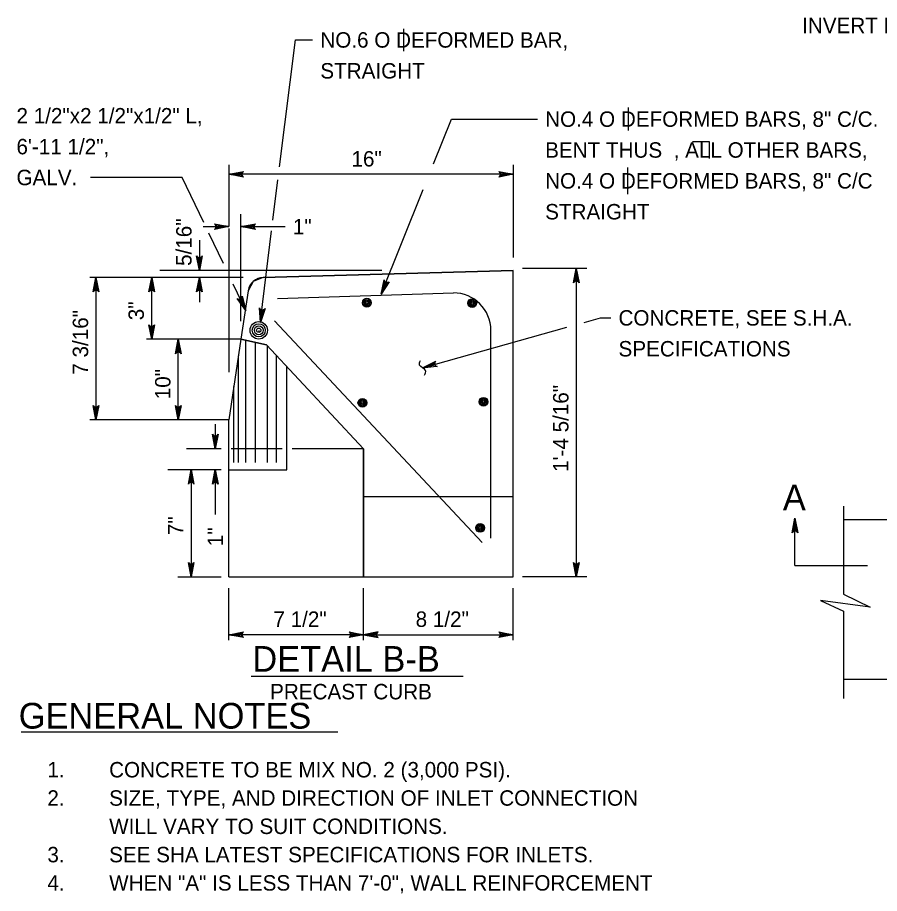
# Model space of a CAD drawing. Extents: x 2.4 to 9.7, y 1.1 to 11.2.
# Drawn here: x 2.448 to 5.797, y 4.792 to 8.197 of the extents above; entities that cross this region are included whole.
import ezdxf

# ---------------------------------------------------------------- set-up
doc = ezdxf.new("R2010")
doc.units = 0
for name, color, linetype in [('DETL-DIMS', 7, 'Continuous'), ('DETL-LINE', 7, 'Continuous'), ('DETL-NOTE', 7, 'Continuous'), ('DETL-PATT', 7, 'Continuous'), ('DETL-TITL', 7, 'Continuous')]:
    doc.layers.add(name, color=color, linetype=linetype)

msp = doc.modelspace()

# ---------------------------------------------------------------- linework, layer by layer
at = {"layer": 'DETL-DIMS'}
for p, q in [((3.466, 7.6169), (3.5274, 8.1102)), ((3.5274, 8.1102), (3.5939, 8.1102)), ((4.064, 7.6283), (4.134, 7.8024)), ((4.134, 7.8024), (4.4675, 7.8024)), ((3.2692, 7.6252), (3.2692, 7.3843)), ((4.3741, 7.6252), (4.3741, 7.265)), ((3.0872, 7.5755), (2.7316, 7.5755)), ((3.1714, 7.4), (3.0872, 7.5755)), ((4.3741, 7.5878), (3.2692, 7.5878)), ((3.4402, 7.4102), (3.4597, 7.5668)), ((3.8604, 7.1217), (4.0242, 7.5292)), ((3.3158, 7.017), (3.3158, 7.4334)), ((3.1685, 7.3843), (3.2692, 7.3843)), ((3.2478, 7.2406), (3.1908, 7.3595)), ((3.2692, 7.3772), (3.2692, 6.8182)), ((3.3158, 7.3843), (3.4874, 7.3843)), ((3.3927, 7.0288), (3.4349, 7.3676)), ((3.1543, 7.3314), (3.1543, 7.214)), ((4.6598, 7.222), (4.4098, 7.222)), ((4.6187, 7.222), (4.6187, 6.0227)), ((3.3242, 7.1873), (2.7288, 7.1873)), ((2.7524, 7.1873), (2.7524, 6.6331)), ((2.969, 6.9464), (2.969, 7.1873)), ((3.8631, 7.214), (3.0002, 7.214)), ((3.1543, 7.1873), (3.1543, 7.0908)), ((3.335, 7.0585), (3.2862, 7.1605)), ((4.6497, 7.0121), (4.7123, 7.0297)), ((4.7123, 7.0297), (4.7525, 7.0297)), ((3.3859, 6.9743), (3.3867, 6.9812)), ((4.0216, 6.8356), (4.5823, 6.9932)), ((3.316, 6.9464), (2.9483, 6.9464)), ((3.0724, 6.6331), (3.0724, 6.9464)), ((3.2692, 6.6331), (2.7288, 6.6331)), ((3.2162, 6.6167), (3.2162, 6.5207)), ((3.2395, 6.5207), (3.1038, 6.5207)), ((3.4756, 6.5207), (3.2777, 6.5207)), ((3.7923, 6.5207), (3.5142, 6.5207)), ((3.0316, 6.44), (3.2395, 6.44)), ((3.1221, 6.44), (3.1221, 6.0227)), ((3.2162, 6.44), (3.2162, 6.2651)), ((5.4685, 6.0667), (5.4683, 6.2512)), ((5.4685, 6.0667), (5.7503, 6.0671)), ((3.0705, 6.0227), (3.2395, 6.0227)), ((4.6598, 6.0227), (4.4098, 6.0227)), ((3.2692, 5.7764), (3.2692, 5.9792)), ((3.7923, 5.7764), (3.7923, 5.9792)), ((4.3741, 5.7764), (4.3741, 5.9792)), ((3.7923, 5.7981), (3.2692, 5.7981)), ((3.7923, 5.7981), (4.3741, 5.7981))]:
    msp.add_line(p, q, dxfattribs=at)
for points in [[(3.2692, 7.5878), (3.3257, 7.5983), (3.3213, 7.5953), (3.3191, 7.5915), (3.3185, 7.5878), (3.3191, 7.584), (3.3213, 7.5802), (3.3257, 7.5772), (3.2692, 7.5878), (3.3213, 7.5802), (3.3191, 7.584), (3.2692, 7.5878), (3.3185, 7.5878), (3.3191, 7.5915), (3.2692, 7.5878), (3.3213, 7.5953)], [(4.3741, 7.5878), (4.3176, 7.5772), (4.322, 7.5802), (4.3242, 7.584), (4.3249, 7.5878), (4.3242, 7.5915), (4.322, 7.5953), (4.3176, 7.5983), (4.3741, 7.5878), (4.322, 7.5953), (4.3242, 7.5915), (4.3741, 7.5878), (4.3249, 7.5878), (4.3242, 7.584), (4.3741, 7.5878), (4.322, 7.5802)], [(3.2692, 7.3843), (3.2127, 7.3737), (3.2171, 7.3767), (3.2193, 7.3805), (3.22, 7.3843), (3.2193, 7.388), (3.2171, 7.3918), (3.2127, 7.3948), (3.2692, 7.3843), (3.2171, 7.3918), (3.2193, 7.388), (3.2692, 7.3843), (3.22, 7.3843), (3.2193, 7.3805), (3.2692, 7.3843), (3.2171, 7.3767)], [(3.3158, 7.3843), (3.3722, 7.3948), (3.3679, 7.3918), (3.3657, 7.388), (3.365, 7.3843), (3.3657, 7.3805), (3.3679, 7.3767), (3.3722, 7.3737), (3.3158, 7.3843), (3.3679, 7.3767), (3.3657, 7.3805), (3.3158, 7.3843), (3.365, 7.3843), (3.3657, 7.388), (3.3158, 7.3843), (3.3679, 7.3918)], [(3.1543, 7.214), (3.1437, 7.2705), (3.1467, 7.2661), (3.1505, 7.2639), (3.1543, 7.2632), (3.1581, 7.2639), (3.1619, 7.2661), (3.1649, 7.2705), (3.1543, 7.214), (3.1619, 7.2661), (3.1581, 7.2639), (3.1543, 7.214), (3.1543, 7.2632), (3.1505, 7.2639), (3.1543, 7.214), (3.1467, 7.2661)], [(4.6187, 7.222), (4.6293, 7.1655), (4.6263, 7.1698), (4.6225, 7.1721), (4.6187, 7.1727), (4.6149, 7.1721), (4.6112, 7.1698), (4.6081, 7.1655), (4.6187, 7.222), (4.6112, 7.1698), (4.6149, 7.1721), (4.6187, 7.222), (4.6187, 7.1727), (4.6225, 7.1721), (4.6187, 7.222), (4.6263, 7.1698)], [(2.7524, 7.1873), (2.763, 7.1308), (2.7599, 7.1352), (2.7562, 7.1374), (2.7524, 7.1381), (2.7486, 7.1374), (2.7448, 7.1352), (2.7418, 7.1308), (2.7524, 7.1873), (2.7448, 7.1352), (2.7486, 7.1374), (2.7524, 7.1873), (2.7524, 7.1381), (2.7562, 7.1374), (2.7524, 7.1873), (2.7599, 7.1352)], [(2.969, 7.1873), (2.9796, 7.1308), (2.9766, 7.1352), (2.9728, 7.1374), (2.969, 7.1381), (2.9652, 7.1374), (2.9615, 7.1352), (2.9584, 7.1308), (2.969, 7.1873), (2.9615, 7.1352), (2.9652, 7.1374), (2.969, 7.1873), (2.969, 7.1381), (2.9728, 7.1374), (2.969, 7.1873), (2.9766, 7.1352)], [(3.1543, 7.1873), (3.1649, 7.1308), (3.1619, 7.1352), (3.1581, 7.1374), (3.1543, 7.1381), (3.1505, 7.1374), (3.1467, 7.1352), (3.1437, 7.1308), (3.1543, 7.1873), (3.1467, 7.1352), (3.1505, 7.1374), (3.1543, 7.1873), (3.1543, 7.1381), (3.1581, 7.1374), (3.1543, 7.1873), (3.1619, 7.1352)], [(3.8604, 7.1217), (3.8717, 7.1781), (3.8729, 7.1729), (3.8755, 7.1694), (3.8788, 7.1674), (3.8826, 7.1666), (3.8869, 7.1672), (3.8913, 7.1702), (3.8604, 7.1217), (3.8869, 7.1672), (3.8826, 7.1666), (3.8604, 7.1217), (3.8788, 7.1674), (3.8755, 7.1694), (3.8604, 7.1217), (3.8729, 7.1729)], [(3.335, 7.0585), (3.3011, 7.1049), (3.3057, 7.1023), (3.3101, 7.1019), (3.3138, 7.1029), (3.3169, 7.1052), (3.3193, 7.1088), (3.3202, 7.1141), (3.335, 7.0585), (3.3193, 7.1088), (3.3169, 7.1052), (3.335, 7.0585), (3.3138, 7.1029), (3.3101, 7.1019), (3.335, 7.0585), (3.3057, 7.1023)], [(3.3918, 7.0116), (3.3883, 7.0689), (3.3908, 7.0642), (3.3943, 7.0615), (3.3979, 7.0604), (3.4018, 7.0606), (3.4058, 7.0624), (3.4093, 7.0663), (3.3918, 7.0116), (3.4058, 7.0624), (3.4018, 7.0606), (3.3918, 7.0116), (3.3979, 7.0604), (3.3943, 7.0615), (3.3918, 7.0116), (3.3908, 7.0642)], [(2.969, 6.9464), (2.9584, 7.0029), (2.9615, 6.9985), (2.9652, 6.9963), (2.969, 6.9956), (2.9728, 6.9963), (2.9766, 6.9985), (2.9796, 7.0029), (2.969, 6.9464), (2.9766, 6.9985), (2.9728, 6.9963), (2.969, 6.9464), (2.969, 6.9956), (2.9652, 6.9963), (2.969, 6.9464), (2.9615, 6.9985)], [(3.0724, 6.9464), (3.083, 6.8899), (3.0799, 6.8943), (3.0761, 6.8965), (3.0724, 6.8972), (3.0686, 6.8965), (3.0648, 6.8943), (3.0618, 6.8899), (3.0724, 6.9464), (3.0648, 6.8943), (3.0686, 6.8965), (3.0724, 6.9464), (3.0724, 6.8972), (3.0761, 6.8965), (3.0724, 6.9464), (3.0799, 6.8943)], [(4.0216, 6.8356), (4.0731, 6.8611), (4.0697, 6.857), (4.0686, 6.8528), (4.069, 6.8489), (4.0706, 6.8455), (4.0738, 6.8424), (4.0788, 6.8407), (4.0216, 6.8356), (4.0738, 6.8424), (4.0706, 6.8455), (4.0216, 6.8356), (4.069, 6.8489), (4.0686, 6.8528), (4.0216, 6.8356), (4.0697, 6.857)], [(2.7524, 6.6331), (2.7418, 6.6896), (2.7448, 6.6852), (2.7486, 6.683), (2.7524, 6.6823), (2.7562, 6.683), (2.7599, 6.6852), (2.763, 6.6896), (2.7524, 6.6331), (2.7599, 6.6852), (2.7562, 6.683), (2.7524, 6.6331), (2.7524, 6.6823), (2.7486, 6.683), (2.7524, 6.6331), (2.7448, 6.6852)], [(3.0724, 6.6331), (3.0618, 6.6896), (3.0648, 6.6852), (3.0686, 6.683), (3.0724, 6.6823), (3.0761, 6.683), (3.0799, 6.6852), (3.083, 6.6896), (3.0724, 6.6331), (3.0799, 6.6852), (3.0761, 6.683), (3.0724, 6.6331), (3.0724, 6.6823), (3.0686, 6.683), (3.0724, 6.6331), (3.0648, 6.6852)], [(3.2162, 6.5207), (3.2056, 6.5771), (3.2086, 6.5728), (3.2124, 6.5705), (3.2162, 6.5699), (3.22, 6.5705), (3.2238, 6.5728), (3.2268, 6.5771), (3.2162, 6.5207), (3.2238, 6.5728), (3.22, 6.5705), (3.2162, 6.5207), (3.2162, 6.5699), (3.2124, 6.5705), (3.2162, 6.5207), (3.2086, 6.5728)], [(3.1221, 6.44), (3.1327, 6.3835), (3.1296, 6.3879), (3.1259, 6.3901), (3.1221, 6.3908), (3.1183, 6.3901), (3.1145, 6.3879), (3.1115, 6.3835), (3.1221, 6.44), (3.1145, 6.3879), (3.1183, 6.3901), (3.1221, 6.44), (3.1221, 6.3908), (3.1259, 6.3901), (3.1221, 6.44), (3.1296, 6.3879)], [(3.2162, 6.44), (3.2268, 6.3835), (3.2238, 6.3879), (3.22, 6.3901), (3.2162, 6.3908), (3.2124, 6.3901), (3.2086, 6.3879), (3.2056, 6.3835), (3.2162, 6.44), (3.2086, 6.3879), (3.2124, 6.3901), (3.2162, 6.44), (3.2162, 6.3908), (3.22, 6.3901), (3.2162, 6.44), (3.2238, 6.3879)], [(5.4683, 6.2512), (5.479, 6.1947), (5.4759, 6.199), (5.4721, 6.2013), (5.4684, 6.2019), (5.4646, 6.2013), (5.4608, 6.199), (5.4578, 6.1947), (5.4683, 6.2512), (5.4608, 6.199), (5.4646, 6.2013), (5.4683, 6.2512), (5.4684, 6.2019), (5.4721, 6.2013), (5.4683, 6.2512), (5.4759, 6.199)], [(3.1221, 6.0227), (3.1115, 6.0792), (3.1145, 6.0748), (3.1183, 6.0726), (3.1221, 6.0719), (3.1259, 6.0726), (3.1296, 6.0748), (3.1327, 6.0792), (3.1221, 6.0227), (3.1296, 6.0748), (3.1259, 6.0726), (3.1221, 6.0227), (3.1221, 6.0719), (3.1183, 6.0726), (3.1221, 6.0227), (3.1145, 6.0748)], [(4.6187, 6.0227), (4.6081, 6.0792), (4.6112, 6.0748), (4.6149, 6.0726), (4.6187, 6.0719), (4.6225, 6.0726), (4.6263, 6.0748), (4.6293, 6.0792), (4.6187, 6.0227), (4.6263, 6.0748), (4.6225, 6.0726), (4.6187, 6.0227), (4.6187, 6.0719), (4.6149, 6.0726), (4.6187, 6.0227), (4.6112, 6.0748)], [(5.6575, 5.9558), (5.7602, 5.9055), (5.568, 5.9316), (5.6575, 5.8891)], [(3.2692, 5.7981), (3.3257, 5.8087), (3.3213, 5.8057), (3.3191, 5.8019), (3.3185, 5.7981), (3.3191, 5.7944), (3.3213, 5.7906), (3.3257, 5.7876), (3.2692, 5.7981), (3.3213, 5.7906), (3.3191, 5.7944), (3.2692, 5.7981), (3.3185, 5.7981), (3.3191, 5.8019), (3.2692, 5.7981), (3.3213, 5.8057)], [(3.7923, 5.7981), (3.7358, 5.7876), (3.7402, 5.7906), (3.7424, 5.7944), (3.7431, 5.7981), (3.7424, 5.8019), (3.7402, 5.8057), (3.7358, 5.8087), (3.7923, 5.7981), (3.7402, 5.8057), (3.7424, 5.8019), (3.7923, 5.7981), (3.7431, 5.7981), (3.7424, 5.7944), (3.7923, 5.7981), (3.7402, 5.7906)], [(3.7923, 5.7981), (3.8488, 5.7876), (3.8445, 5.7906), (3.8422, 5.7944), (3.8416, 5.7981), (3.8422, 5.8019), (3.8445, 5.8057), (3.8488, 5.8087), (3.7923, 5.7981), (3.8445, 5.8057), (3.8422, 5.8019), (3.7923, 5.7981), (3.8416, 5.7981), (3.8422, 5.7944), (3.7923, 5.7981), (3.8445, 5.7906)], [(4.3741, 5.7981), (4.3176, 5.7876), (4.322, 5.7906), (4.3242, 5.7944), (4.3249, 5.7981), (4.3242, 5.8019), (4.322, 5.8057), (4.3176, 5.8087), (4.3741, 5.7981), (4.322, 5.8057), (4.3242, 5.8019), (4.3741, 5.7981), (4.3249, 5.7981), (4.3242, 5.7944), (4.3741, 5.7981), (4.322, 5.7906)]]:
    msp.add_lwpolyline(points, dxfattribs=at)
msp.add_spline([(4.029, 6.807), (4.033, 6.8251), (4.0101, 6.8462), (4.0132, 6.8639)], degree=3, dxfattribs=at)
at = {"layer": 'DETL-LINE'}
for p, q in [((3.4025, 7.187), (4.3741, 7.214)), ((4.3741, 6.0227), (4.3741, 7.214)), ((3.3442, 7.1353), (3.316, 6.9464)), ((3.4584, 7.1053), (4.1414, 7.1267)), ((4.2529, 6.156), (3.4462, 7.0186)), ((4.2869, 6.1737), (4.2869, 6.9813)), ((3.316, 6.9464), (3.2692, 6.6331)), ((3.4149, 6.9243), (3.316, 6.9464)), ((3.3351, 6.467), (3.3351, 6.9421)), ((3.3726, 6.467), (3.3726, 6.9337)), ((3.7923, 6.5207), (3.4149, 6.9243)), ((3.419, 6.467), (3.419, 6.9198)), ((3.3063, 6.467), (3.3063, 6.8818)), ((3.4543, 6.467), (3.4543, 6.882)), ((3.4938, 6.4388), (3.4938, 6.8398)), ((3.2887, 6.467), (3.2887, 6.7634)), ((3.2692, 6.0227), (3.2692, 6.6331)), ((3.7923, 6.0227), (3.7923, 6.5207)), ((3.2692, 6.4388), (3.4938, 6.4388)), ((3.7923, 6.3357), (4.3741, 6.3357)), ((5.6575, 6.2975), (5.6575, 5.9558)), ((6.0058, 6.2449), (5.6575, 6.2449)), ((3.2692, 6.0227), (4.3741, 6.0227)), ((5.6575, 5.8891), (5.6575, 5.5495)), ((6.0058, 5.6245), (5.6575, 5.6245))]:
    msp.add_line(p, q, dxfattribs=at)
for centre, radius in [((3.8053, 7.0888), 0.017), ((3.8053, 7.0888), 0.0127), ((3.8053, 7.0888), 0.00848), ((3.8053, 7.0888), 0.00424), ((4.2146, 7.0872), 0.017), ((4.2146, 7.0872), 0.0127), ((4.2146, 7.0872), 0.00848), ((4.2146, 7.0872), 0.00424), ((3.385, 6.9814), 0.0339), ((3.385, 6.9814), 0.0255), ((3.385, 6.9814), 0.017), ((3.385, 6.9814), 0.00848), ((3.7876, 6.6994), 0.017), ((3.7876, 6.6994), 0.0127), ((4.2583, 6.7038), 0.017), ((4.2583, 6.7038), 0.0127), ((4.2583, 6.7038), 0.00848), ((3.7876, 6.6994), 0.00848), ((3.7876, 6.6994), 0.00424), ((4.2583, 6.7038), 0.00424), ((4.2449, 6.2132), 0.017), ((4.2449, 6.2132), 0.0127), ((4.2449, 6.2132), 0.00848), ((4.2449, 6.2132), 0.00424)]:
    msp.add_circle(centre, radius, dxfattribs=at)
for centre, radius, start, end in [((3.4041, 7.1264), 0.0606, 91.5948, 171.5078), ((4.1414, 6.9813), 0.1455, 0, 90)]:
    msp.add_arc(centre, radius, start, end, dxfattribs=at)
at = {"layer": 'DETL-NOTE'}
for p, q in [((3.947, 8.1539), (3.947, 8.0664)), ((4.8197, 7.8471), (4.8197, 7.7576)), ((5.0698, 7.7152), (5.1347, 7.7152)), ((5.1347, 7.7152), (5.1347, 7.6496)), ((4.818, 7.6145), (4.818, 7.5102)), ((2.4624, 5.4204), (3.6925, 5.4204))]:
    msp.add_line(p, q, dxfattribs=at)
at = {"layer": 'DETL-PATT'}
msp.add_lwpolyline([(3.7923, 6.0227), (4.3741, 6.0227), (4.3741, 7.214), (3.4025, 7.187), (3.3639, 7.1717), (3.3442, 7.1353), (3.316, 6.9464), (3.4149, 6.9243), (3.7923, 6.5207)], close=True, dxfattribs=at)
at = {"layer": 'DETL-TITL'}
msp.add_line((3.3559, 5.6373), (4.1798, 5.6373), dxfattribs=at)

# ---------------------------------------------------------------- texts
at = {"layer": 'DETL-NOTE'}
for s, height, p in [('INVERT MAY BE PLAIN CONCRETE OR 4" BRICK LAID ON EDGE.', 0.06, (5.4964, 8.1365)), ('NO.6 O DEFORMED BAR,', 0.06, (3.6243, 8.0802)), ('STRAIGHT', 0.06, (3.6243, 7.9602)), ('2 1/2"x2 1/2"x1/2" L,', 0.06, (2.4437, 7.7855)), ('NO.4 O DEFORMED BARS, 8" C/C. ', 0.06, (4.4978, 7.7724)), ('6\'-11 1/2",', 0.06, (2.4437, 7.6655)), ('BENT THUS  , ALL OTHER BARS,', 0.06, (4.4978, 7.6524)), ('16"', 0.06, (3.7453, 7.6181)), ('GALV.', 0.06, (2.4437, 7.5455)), ('NO.4 O DEFORMED BARS, 8" C/C', 0.06, (4.4978, 7.5324)), ('STRAIGHT', 0.06, (4.4978, 7.4124)), ('1"', 0.06, (3.5177, 7.3543)), ('CONCRETE, SEE S.H.A.', 0.06, (4.7828, 6.9997)), ('SPECIFICATIONS', 0.06, (4.7828, 6.8797)), ('7 1/2"', 0.06, (3.442, 5.8284)), ('8 1/2"', 0.06, (3.9945, 5.8284)), ('PRECAST CURB', 0.06, (3.4291, 5.5467)), ('GENERAL NOTES', 0.1, (2.4523, 5.433)), ('1.', 0.06, (2.5637, 5.2432)), ('CONCRETE TO BE MIX NO. 2 (3,000 PSI).', 0.06, (2.8037, 5.2432)), ('2.', 0.06, (2.5637, 5.1332)), ('SIZE, TYPE, AND DIRECTION OF INLET CONNECTION ', 0.06, (2.8037, 5.1332)), ('WILL VARY TO SUIT CONDITIONS.', 0.06, (2.8037, 5.0232)), ('3.', 0.06, (2.5637, 4.9132)), ('SEE SHA LATEST SPECIFICATIONS FOR INLETS.', 0.06, (2.8037, 4.9132)), ('4.', 0.06, (2.5637, 4.8032)), ('WHEN "A" IS LESS THAN 7\'-0", WALL REINFORCEMENT ', 0.06, (2.8037, 4.8032))]:
    msp.add_text(s, height=height, dxfattribs=at).set_placement(p)
for s, p in [('5/16"', (3.124, 7.2317)), ('3"', (2.9387, 7.0205)), ('7 3/16"', (2.7221, 6.8089)), ('10"', (3.0421, 6.7134)), ('1\'-4 5/16"', (4.5884, 6.431)), ('7"', (3.0918, 6.185)), ('1"', (3.2462, 6.1421))]:
    msp.add_text(s, height=0.06, rotation=90, dxfattribs=at).set_placement(p)
at = {"layer": 'DETL-TITL'}
for s, p in [('A', (5.4213, 6.2815)), ('DETAIL B-B', (3.3601, 5.654))]:
    msp.add_text(s, height=0.1, dxfattribs=at).set_placement(p)

doc.saveas('drawing.dxf')
